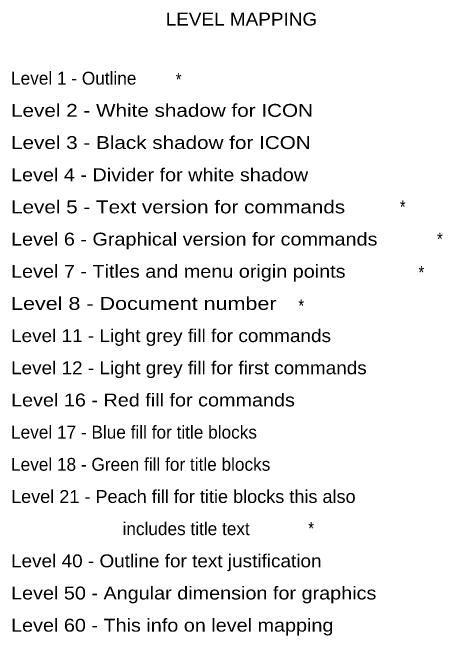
# Model space of a CAD drawing. Extents: x 95906.8 to 95923.6, y 90964.8 to 90972.8.
# Drawn here: x 95920.255 to 95923.596, y 90968.008 to 90972.849 of the extents above; entities that cross this region are included whole.
import ezdxf
from ezdxf.enums import TextEntityAlignment as Align

# ---------------------------------------------------------------- set-up
doc = ezdxf.new("R2010")
doc.units = 0
doc.header["$LTSCALE"] = 0.019
doc.layers.add('60', color=7, linetype='Continuous')

msp = doc.modelspace()

# ---------------------------------------------------------------- texts
at = {"layer": '60', "width": 1.1}
msp.add_text('LEVEL MAPPING', height=0.1, dxfattribs=at).set_placement((95922.0332, 90972.7477), align=Align.CENTER)
at = {"layer": '60'}
for s, p in [('Level 1 - Outline', (95920.2436, 90972.2883)), ('Level 17 - Blue fill for title blocks', (95920.2436, 90969.5383)), ('Level 18 - Green fill for title blocks', (95920.2436, 90969.2883)), ('includes title text', (95921.1095, 90968.7883))]:
    msp.add_text(s, height=0.1, dxfattribs=at).set_placement(p)
for s, width, p in [('*', 0.85, (95921.5232, 90972.2787)), ('Level 2 - White shadow for ICON', 1.2, (95920.2436, 90972.0383)), ('Level 3 - Black shadow for ICON', 1.2, (95920.2436, 90971.7883)), ('Level 4 - Divider for white shadow', 1.15, (95920.2436, 90971.5383)), ('Level 5 - Text version for commands', 1.2, (95920.2436, 90971.2883)), ('*', 0.85, (95923.2645, 90971.2889)), ('Level 6 - Graphical version for commands', 1.15, (95920.2436, 90971.0383)), ('*', 0.85, (95923.5531, 90971.0391)), ('Level 7 - Titles and menu origin points', 1.15, (95920.2436, 90970.7883)), ('*', 0.85, (95923.4089, 90970.7795)), ('Level 8 - Document number', 1.25, (95920.2436, 90970.5383)), ('*', 0.85, (95922.4756, 90970.5201)), ('Level 11 - Light grey fill for commands', 1.1, (95920.2436, 90970.2883)), ('Level 12 - Light grey fill for first commands', 1.1, (95920.2436, 90970.0383)), ('Level 16 - Red fill for commands', 1.15, (95920.2436, 90969.7883)), ('Level 21 - Peach fill for titie blocks this also', 1.05, (95920.2436, 90969.0383)), ('*', 0.85, (95922.5526, 90968.7902)), ('Level 40 - Outline for text justification', 1.1, (95920.2436, 90968.5383)), ('Level 50 - Angular dimension for graphics', 1.15, (95920.2436, 90968.2883)), ('Level 60 - This info on level mapping', 1.15, (95920.2436, 90968.0383))]:
    msp.add_text(s, height=0.1, dxfattribs=dict(at, width=width)).set_placement(p)

doc.saveas('drawing.dxf')
